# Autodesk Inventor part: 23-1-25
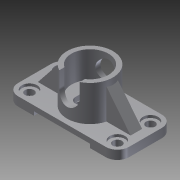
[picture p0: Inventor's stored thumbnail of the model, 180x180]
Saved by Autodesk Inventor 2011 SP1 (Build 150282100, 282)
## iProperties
Created: 2014-01
Part Number: 23-1-25
Document SubType Name: Modeling
Designer: Administrator
Density: 1 g/cm^3
Author: Administrator
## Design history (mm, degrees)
sketch "草图1"
  geometry: L1 (-34.5, 22)-(34.5, 22); L2 (43.5, 13)-(43.5, -13); L3 (34.5, -22)-(-34.5, -22); L4 (-43.5, -13)-(-43.5, 13); A1 r 9 centre (-34.5, 13) between (-34.5, 22) and (-43.5, 13); A2 r 9 centre (-34.5, -13) between (-43.5, -13) and (-34.5, -22); A3 r 9 centre (34.5, -13) between (34.5, -22) and (43.5, -13); A4 r 9 centre (34.5, 13) between (43.5, 13) and (34.5, 22); 6 further points
  constraints: 8 end point, 8 point on circle, 8 tangent, 6 point on line, 4 centre point, 3 equal radius, 2 midpoint, 2 parallel, 1 horizontal, 1 horizontal alignment, 1 perpendicular, 1 vertical alignment
  dimensions: "d0" = 87 distance of point (-43.5, 22) point (43.5, 22); "d1" = 44 distance of point (43.5, 22) point (43.5, -22); "d2" = 9 radius of A1
extrude "拉伸1" new body sketch "草图1" distance "d3" = 7; taper "d4" = 0 deg
sketch "草图2"
  geometry: L1 (-34.5, -22)-(34.5, -22) reference; L2 (22, -22)-(-22, -22); L3 (-22, -22)-(-22, 22); L4 (-22, 22)-(22, 22); L5 (22, 22)-(22, -22); 2 further points
  constraints: 8 end point, 2 midpoint, 2 parallel, 1 horizontal, 1 perpendicular
  dimensions: "d5" = 44 distance of L2.end L3.end; "d6" = 44 distance of L2.start L2.end
extrude "拉伸2" cut sketch "草图2" distance "d7" = 3; taper "d8" = 0 deg
hole "Hole1" diameter "d11" = 7; stored, may be unused: countersink angle "d15" = 90 deg, drill point angle "d17" = 118 deg; dims "d9" = 10, "d10" = 10, "d12" = 6, "d13" = 12, "d14" = 2, "d16" = 8
mirror "镜像1"
mirror "镜像2"
sketch "草图3"
  geometry: C1 r 18 at (0, 0); 1 further point
  constraints: 1 centre point, 1 coincident
  dimensions: "d18" = 36 diameter of C1
extrude "拉伸3" join sketch "草图3" distance "d19" = 28; taper "d20" = 0 deg
hole "Hole2" diameter "d23" = 29; stored, may be unused: countersink angle "d27" = 90 deg, drill point angle "d29" = 0 deg; dims "d21" = 10, "d22" = 10, "d24" = 6, "d25" = 12, "d26" = 2, "d28" = 21
node "工作平面1"
sketch "草图4"
  geometry: L1 (-18, 35)-(18, 35) reference; L2 (-8, 23)-(-8, 35); L3 (8, 23)-(8, 35); A1 r 8 centre (0, 23) between (-8, 23) and (8, 23); 1 further point
  constraints: 4 end point, 2 perpendicular, 2 point on circle, 2 point on line, 2 tangent, 1 centre point
  dimensions: "d31" = 16 diameter of A1; "d32" = 12 distance from line of L1 A1.centre
extrude "拉伸4" cut sketch "草图4" distance "d33" = 7; taper "d34" = 0 deg
sketch "草图5"
  geometry: 4 further points
  constraints: 1 vertical alignment, 3 other
extrude "拉伸5" cut sketch "草图5" distance "d35" = 40; taper "d36" = 0 deg
sketch "草图6"
  geometry: L1 (-8.5, 9)-(8.5, 9); L2 (8.5, 9)-(8.5, 3); L3 (-8.5, 3)-(-8.5, 9); L4 (-4.5, 3)-(4.5, 3); L5 (4.5, 3)-(4.5, -7); L6 (4.5, -7)-(-4.5, -7); L7 (-4.5, -7)-(-4.5, 3); L8 (8.5, 3)-(4.5, 3); L9 (-4.5, 3)-(-8.5, 3); C1 r 14.5 at (0, 0) reference; 2 further points
  constraints: 18 end point, 5 parallel, 2 horizontal, 2 midpoint, 2 perpendicular, 1 vertical alignment
  dimensions: "d37" = 17 distance of L1.start L1.end; "d38" = 6 distance of L3.start L1.start; "d39" = 9 distance of C1.centre point (0, 9); "d40" = 10 distance of L4.end L5.end; "d41" = 9 distance of L5.end L6.end
extrude "拉伸6" cut sketch "草图6" distance "d42" = 4; taper "d43" = 0 deg
sketch "草图7"
  geometry: L1 (8.5, 3)-(-8.5, 3) reference; L2 (-4.5, 3)-(4.5, 3); L3 (4.5, 3)-(4.5, -7); L4 (4.5, -7)-(-4.5, -7); L5 (-4.5, -7)-(-4.5, 3); 1 further point
  constraints: 8 end point, 2 midpoint, 2 parallel, 1 horizontal, 1 perpendicular
  dimensions: "d44" = 9 distance of L3.end L4.end; "d45" = 10 distance of L2.end L3.end
extrude "拉伸7" cut sketch "草图7" distance "d46" = 4; taper "d47" = 0 deg
sketch "草图8"
  geometry: L1 (4.5, -7)-(-4.5, -7) reference; 1 further point
  constraints: 1 midpoint
hole "Hole3" sketch "草图8" at (0, -7) diameter "d48" = 9; stored, may be unused: countersink angle "d52" = 90 deg, drill point angle "d54" = 118 deg; dims "d49" = 6, "d50" = 12, "d51" = 2, "d53" = 21
sketch "草图9"
  geometry: L1 (18, 7)-(18, 35) reference; L2 (34.5, 7)-(-34.5, 7) reference; L3 (28.5, 7)-(40.5, 7) reference; L4 (34.5, 7)-(43.5, 7) reference; L5 (38, 0)-(38, 5) reference; L6 (18, 30)-(36.4, 7); 1 further point
  constraints: 2 end point, 2 point on line
  dimensions: "d55" = 5 distance of L6.start L1.end
feature "加强筋1" sketch "草图9" dims "d56" = 1, "d57" = 9, "d58" = 0
mirror "镜像3"
node "实体1"
other parameters: "d30" = -18
